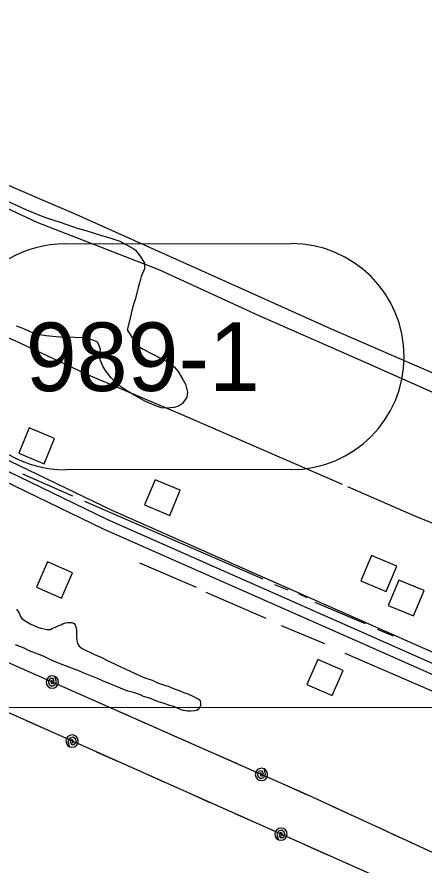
# Model space of a CAD drawing. Extents: x 3297735 to 3335592, y 670436 to 695807.
# Drawn here: x 3304933 to 3305528, y 684677 to 685915 of the extents above; entities that cross this region are included whole.
import ezdxf

# ---------------------------------------------------------------- set-up
doc = ezdxf.new("R2010")
doc.units = 0
for name, color, linetype in [('V-BLDG-OTLN', 7, 'Continuous'), ('V-DTCH-CNTR', 7, 'Continuous'), ('V-GRID-MAJR', 7, 'Continuous'), ('V-ROAD-CNTR', 7, 'Continuous'), ('V-ROAD-IDEN', 7, 'Continuous'), ('V-SITE-VEGE', 7, 'Continuous'), ('V-TOPO-SHOR', 7, 'Continuous'), ('V-UTIL-LINE', 7, 'Continuous')]:
    doc.layers.add(name, color=color, linetype=linetype)

msp = doc.modelspace()

# ---------------------------------------------------------------- linework, layer by layer
at = {"layer": 'V-BLDG-OTLN'}
for points in [[(3304935.6, 685277.8), (3304972.5, 685262.4), (3304987.9, 685299.4), (3304951, 685314.7)], [(3305119.4, 685202.3), (3305156.3, 685186.9), (3305171.6, 685223.9), (3305134.7, 685239.2)], [(3305435.5, 685091.4), (3305472.4, 685076.1), (3305487.8, 685113), (3305450.8, 685128.3)], [(3305014.1, 685103), (3304977.5, 685119.1), (3304961.4, 685082.4), (3304998.1, 685066.4)], [(3305475.4, 685055.6), (3305512.3, 685040.2), (3305527.7, 685077.2), (3305490.8, 685092.5)], [(3305409.4, 684960.8), (3305372.7, 684976.8), (3305356.7, 684940.2), (3305393.3, 684924.1)]]:
    msp.add_lwpolyline(points, close=True, dxfattribs=at)
at = {"layer": 'V-DTCH-CNTR'}
msp.add_lwpolyline([(3305722.8, 685316.5), (3305549.7, 685390.9), (3305392.7, 685459.1), (3305208.3, 685541.7), (3305020.5, 685626), (3304765.5, 685734.7), (3304672, 685772.5), (3304659.7, 685783.2), (3304657.1, 685791.1), (3304658.1, 685807.9), (3304671.6, 685853), (3304716.5, 685957)], dxfattribs=at)
at = {"layer": 'V-GRID-MAJR'}
msp.add_lwpolyline([(3333388.2, 684936.3), (3332676.5, 684935.3), (3330154.9, 684931.8), (3328463.2, 684929.5), (3325367.2, 684925.5), (3322941.6, 684922.6), (3320771, 684920.2), (3318377.2, 684917.6), (3316653.7, 684915.8), (3314259.8, 684913.6), (3312823.6, 684912.3), (3310589.3, 684910.3), (3308642.2, 684908.8), (3305993.2, 684906.9), (3303248.2, 684905), (3301856.7, 684904.2)], dxfattribs=at)
at = {"layer": 'V-ROAD-CNTR'}
for points in [[(3307408.2, 684154.4), (3307297.5, 684213.7), (3306973.2, 684342.3), (3306590.8, 684512.8), (3306153.2, 684698.3), (3305849, 684834.1), (3305429.2, 685019.9), (3305065.7, 685180.7), (3304903.3, 685258.9), (3304500.5, 685416), (3304280.3, 685518.8), (3304270.5, 685534.7), (3304263.3, 685546.5), (3304255.6, 685563.9), (3304258.7, 685583), (3304268.3, 685612.2), (3304387, 685867.1)], [(3307415.3, 684167.6), (3307303.9, 684227.3), (3306979, 684356.1), (3306596.8, 684526.6), (3306159.2, 684712), (3305855.1, 684847.8), (3305435.3, 685033.6), (3305072, 685194.3), (3304909.3, 685272.6), (3304506.4, 685429.8), (3304290.7, 685530.4), (3304283.3, 685542.5), (3304276.6, 685553.5), (3304271.1, 685565.9), (3304273.4, 685579.4), (3304282.3, 685606.6), (3304394.6, 685848)], [(3307401.1, 684141.1), (3307291.2, 684200), (3306967.4, 684328.5), (3306584.8, 684499), (3306147.2, 684684.5), (3305842.9, 684820.4), (3305423.1, 685006.2), (3305059.4, 685167.1), (3304897.4, 685245.1), (3304494.6, 685402.2), (3304269.8, 685507.1), (3304257.7, 685526.9), (3304248.9, 685541.4)]]:
    msp.add_lwpolyline(points, dxfattribs=at)
at = {"layer": 'V-ROAD-IDEN'}
for p, q in [((3305003.5, 685583.6), (3305333.5, 685583.9)), ((3305003.5, 685583.6), (3305333.5, 685583.9)), ((3305003.5, 685583.6), (3305003.5, 685583.6)), ((3305333.8, 685253.9), (3305003.8, 685253.6)), ((3305333.8, 685253.9), (3305003.8, 685253.6))]:
    msp.add_line(p, q, dxfattribs=at)
for centre, start, end in [((3305003.7, 685418.6), 90.0584, 270.0584), ((3305003.7, 685418.6), 90.0584, 270.0584), ((3305333.7, 685418.9), 270.0584, 90.0584), ((3305333.7, 685418.9), 270.0584, 90.0584)]:
    msp.add_arc(centre, 165, start, end, dxfattribs=at)
at = {"layer": 'V-SITE-VEGE'}
for points in [[(3304908.8, 685650.4), (3304933.3, 685639.3), (3304947.1, 685633.3), (3304965.9, 685625.5)], [(3304965.9, 685625.5), (3304977.5, 685620.8), (3304994.4, 685615.7), (3305006, 685611.9), (3305020.8, 685606.4), (3305033.7, 685603.1), (3305055.1, 685596.1), (3305067.2, 685592.8), (3305083.3, 685587.2), (3305092.2, 685582.6), (3305103.8, 685576.1), (3305106, 685574.3), (3305113, 685565.3), (3305119.2, 685555.3), (3305119.1, 685546.8), (3305114.4, 685535.7), (3305112.5, 685528.1), (3305110.7, 685521.8), (3305106, 685503.9), (3305102.7, 685493.7), (3305100.8, 685486.1), (3305098.4, 685474.9), (3305094.6, 685460.1), (3305094.6, 685457), (3305096.8, 685453.8), (3305107.3, 685436.7), (3305116.2, 685430.3), (3305119.3, 685428.9), (3305127.8, 685424.3), (3305135.4, 685420.6), (3305145.2, 685415.1), (3305152.3, 685411.4), (3305162.5, 685403.7), (3305168.7, 685397.3), (3305175.3, 685385.6), (3305179.2, 685378.8), (3305182.2, 685367.1), (3305181.2, 685359.5), (3305174.8, 685350.2), (3305168.9, 685346.6), (3305162.6, 685344.5), (3305151.8, 685343.7), (3305143.8, 685344.3), (3305135.7, 685347.1), (3305120.6, 685353.5), (3305108.6, 685360), (3305093.4, 685369.1), (3305084.1, 685375.1), (3305075.2, 685383.7), (3305070.8, 685387.8), (3305063.3, 685396.9), (3305058.9, 685403.7), (3305054.6, 685414), (3305054.2, 685419.9), (3305054.2, 685423.5), (3305054.8, 685429.3), (3305053.5, 685433.8), (3305050.4, 685440.1), (3305045.5, 685442.4), (3305037, 685445.2), (3305029, 685446.2), (3305016.9, 685446.8), (3304996.7, 685447.1), (3304990.4, 685447.6), (3304975.7, 685449.1), (3304966.3, 685450.6), (3304960, 685452.5), (3304950.6, 685455.7), (3304948.9, 685457.1), (3304944.9, 685458.5), (3304940.4, 685460.4), (3304932.4, 685463.1)], [(3304932.4, 685050.2), (3304935.5, 685045.3), (3304938.5, 685038.5), (3304940.7, 685036.2), (3304947.4, 685031.6), (3304952.3, 685028.9), (3304963, 685023.8), (3304967.9, 685022.4), (3304977.3, 685020.5), (3304981.8, 685020.4), (3304984, 685021.8), (3304989.4, 685023.9), (3304993.9, 685026.1), (3304998.4, 685027.8), (3305000.3, 685029.2), (3305004.3, 685030), (3305006.6, 685030.9), (3305013.3, 685030.8), (3305016.4, 685029), (3305018.2, 685026.7), (3305019.5, 685023.1), (3305019.8, 685018.6), (3305019.7, 685007.8), (3305021.4, 684999.8), (3305024, 684996.1), (3305028, 684992.9), (3305046.3, 684984.2), (3305057, 684979.6), (3305064.6, 684975.4), (3305075.3, 684970.4), (3305078.4, 684969), (3305090.9, 684963), (3305098.4, 684959.7), (3305118.5, 684950.5), (3305130.5, 684946.3), (3305138.1, 684942.6), (3305148.4, 684939.4), (3305153.7, 684937.5), (3305162.7, 684933.8), (3305169.8, 684931.5), (3305177.8, 684928.2), (3305182.7, 684926.4), (3305189.9, 684923.1), (3305196.1, 684919.9), (3305199.2, 684918.5), (3305200.5, 684916.3), (3305201, 684913.6), (3305200.9, 684909.5), (3305199.1, 684905.1), (3305195.9, 684902), (3305192.7, 684901.6), (3305186.4, 684901.2), (3305182, 684901.3), (3305176.2, 684902.2), (3305173, 684903.2), (3305162.3, 684907.8), (3305156.1, 684909.7), (3305146.7, 684912.9), (3305139.5, 684914.8), (3305131.5, 684918.1), (3305126.6, 684920.4), (3305117.7, 684922.7), (3305111.9, 684925.5), (3305101.6, 684928.8), (3305094.9, 684930.6), (3305073.5, 684939.4), (3305065.9, 684942.7), (3305058.8, 684945), (3305049.4, 684949.2), (3305041.9, 684952.4), (3305029.8, 684957), (3305023.1, 684960.3), (3304995.9, 684970.5), (3304984.3, 684975.1), (3304972.7, 684981.1), (3304963.8, 684984.4), (3304950.9, 684989.5), (3304943.3, 684993.1), (3304930.8, 684998.2)]]:
    msp.add_lwpolyline(points, dxfattribs=at)
at = {"layer": 'V-TOPO-SHOR'}
for p, q in [((3305014.5, 685215.2), (3304941.3, 685247)), ((3305292.6, 685093.9), (3305032.2, 685207.5)), ((3305195.2, 685081.7), (3305112.5, 685117.2)), ((3305329.2, 685077.7), (3305309.8, 685085.5)), ((3305297.1, 685036.4), (3305209.3, 685074.7)), ((3305357, 685066.6), (3305344.6, 685072.6)), ((3305442.3, 685028.7), (3305368.6, 685060.1)), ((3305382.6, 684999.5), (3305319.7, 685025.9)), ((3305483, 685010.5), (3305459.7, 685020.3)), ((3305604.1, 684902.2), (3305412.5, 684985.6))]:
    msp.add_line(p, q, dxfattribs=at)
for points in [[(3305020.6, 686747.2), (3304941, 686563), (3304886.6, 686439.7), (3304825.3, 686292.3), (3304759.6, 686143.9), (3304688.2, 685980.8), (3304612.5, 685806.3), (3304603.4, 685789.4), (3304599.4, 685784.7), (3304597, 685780), (3304599.1, 685776.2), (3304606.4, 685771.4), (3304725.1, 685725.6), (3304962.1, 685615.2), (3305141.3, 685545.6), (3305286.3, 685478.8), (3305434.9, 685413.8), (3305538.9, 685367.6), (3305706.6, 685293.3), (3305738.8, 685281.8)], [(3305408.5, 685232.2), (3305290.5, 685283.2), (3305174.3, 685333.7), (3305037.7, 685391.6), (3304931.2, 685441.2), (3304788.4, 685501.7), (3304637.6, 685566.7), (3304521.4, 685618.2), (3304516.9, 685619.1), (3304511.5, 685613.8), (3304435.1, 685468)], [(3305631.2, 685138.6), (3305513.2, 685186.5), (3305416.5, 685228.6)]]:
    msp.add_lwpolyline(points, dxfattribs=at)
at = {"layer": 'V-UTIL-LINE'}
for points in [[(3301855.9, 686290.9), (3302508.1, 686015.9), (3303718.5, 685476.3), (3304541.8, 685139.2), (3305359.1, 684778.4), (3306932, 684054.1), (3307415, 683680.5), (3308058.5, 683385.6), (3308857.4, 683018.6), (3310271.9, 682456)], [(3310256.8, 682384.2), (3308755.9, 682962.6), (3307386.3, 683601.8), (3306906.5, 684014.6), (3304924.5, 684897.2), (3303491.5, 685473.4), (3301855.9, 686171)], [(3304917.9, 684973.2), (3304949, 684959.4)], [(3304984.7, 684943.7), (3304984.1, 684946.5), (3304982.5, 684944.8), (3304983.1, 684942.2), (3304985.9, 684941.3), (3304987.4, 684944.3), (3304985.8, 684948.7), (3304981.6, 684948.7), (3304978.5, 684944.9), (3304979.9, 684940.6), (3304983.5, 684937.9), (3304988.2, 684939.2), (3304990.7, 684944.1), (3304988.3, 684951.9), (3304984.9, 684952.7), (3304981.4, 684952.1), (3304978.5, 684950.2), (3304976.4, 684947.3), (3304975.7, 684943.9), (3304976.3, 684940.4), (3304978.2, 684937.5), (3304981, 684935.5), (3304984.5, 684934.7), (3304987.9, 684935.3), (3304990.9, 684937.2), (3304992.9, 684940.1), (3304993.7, 684943.5), (3304993.1, 684946.9), (3304991.2, 684949.9), (3304988.3, 684951.9)], [(3305020.4, 684927.9), (3305051.5, 684914.2)], [(3305088, 684898.1), (3305119.2, 684884.3)], [(3304977.9, 684873.4), (3304946.9, 684887.2)], [(3305155.7, 684868.2), (3305186.8, 684854.4)], [(3305013.5, 684857.5), (3305014.1, 684854.7), (3305015.7, 684856.4), (3305015.1, 684859), (3305012.3, 684859.9), (3305010.8, 684856.9), (3305012.4, 684852.5), (3305016.6, 684852.5), (3305019.7, 684856.3), (3305018.3, 684860.6), (3305014.7, 684863.3), (3305010.1, 684862), (3305007.5, 684857.1), (3305009.9, 684849.3), (3305013.3, 684848.5), (3305016.8, 684849.1), (3305019.7, 684851), (3305021.8, 684853.9), (3305022.5, 684857.3), (3305021.9, 684860.7), (3305020.1, 684863.7), (3305017.2, 684865.7), (3305013.8, 684866.5), (3305010.3, 684865.9), (3305007.4, 684864), (3305005.3, 684861.2), (3305004.5, 684857.7), (3305005.1, 684854.3), (3305007, 684851.3), (3305009.9, 684849.3)], [(3305080.2, 684827.8), (3305049.2, 684841.6)], [(3305223.4, 684838.3), (3305254.5, 684824.6)], [(3305147.8, 684797.7), (3305116.8, 684811.5)], [(3305290.2, 684808.8), (3305289.7, 684811.6), (3305288.1, 684810), (3305288.7, 684807.3), (3305291.4, 684806.4), (3305293, 684809.4), (3305291.4, 684813.9), (3305287.1, 684813.8), (3305284, 684810), (3305285.5, 684805.7), (3305289.1, 684803), (3305293.7, 684804.3), (3305296.2, 684809.2), (3305293.9, 684817), (3305290.4, 684817.8), (3305287, 684817.2), (3305284, 684815.3), (3305282, 684812.4), (3305281.2, 684809), (3305281.8, 684805.6), (3305283.7, 684802.6), (3305286.6, 684800.6), (3305290, 684799.8), (3305293.5, 684800.4), (3305296.4, 684802.3), (3305298.5, 684805.2), (3305299.2, 684808.6), (3305298.6, 684812.1), (3305296.7, 684815), (3305293.9, 684817)], [(3305215.4, 684767.6), (3305184.4, 684781.4)], [(3305325.9, 684793.1), (3305357, 684779.3)], [(3305393.4, 684762.6), (3305424.2, 684748.4)], [(3305283, 684737.5), (3305252, 684751.3)], [(3305460.6, 684731.7), (3305491.5, 684717.5)], [(3305318.7, 684721.7), (3305319.2, 684718.8), (3305320.8, 684720.5), (3305320.2, 684723.2), (3305317.5, 684724.1), (3305315.9, 684721), (3305317.5, 684716.6), (3305321.8, 684716.7), (3305324.9, 684720.4), (3305323.4, 684724.8), (3305319.8, 684727.4), (3305315.2, 684726.1), (3305312.7, 684721.2), (3305315, 684713.4), (3305318.4, 684712.7), (3305321.9, 684713.2), (3305324.9, 684715.1), (3305326.9, 684718), (3305327.7, 684721.4), (3305327.1, 684724.9), (3305325.2, 684727.8), (3305322.3, 684729.9), (3305318.9, 684730.6), (3305315.4, 684730.1), (3305312.5, 684728.2), (3305310.4, 684725.3), (3305309.7, 684721.9), (3305310.3, 684718.4), (3305312.1, 684715.5), (3305315, 684713.4)], [(3305385.4, 684691.9), (3305354.3, 684705.8)]]:
    msp.add_lwpolyline(points, dxfattribs=at)

# ---------------------------------------------------------------- texts
at = {"layer": 'V-ROAD-IDEN'}
msp.add_text('989-1', height=100, rotation=0.0584, dxfattribs=at).set_placement((3304945.9, 685368.5))

doc.saveas('drawing.dxf')
